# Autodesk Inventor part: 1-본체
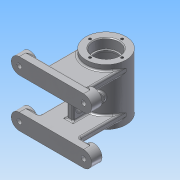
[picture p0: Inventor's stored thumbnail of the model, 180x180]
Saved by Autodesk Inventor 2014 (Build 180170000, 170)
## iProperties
Created: 2015-11
Part Number: 1-본체
Material: 알루미늄 6061
Document SubType Name: Modeling
Designer: 106-16
Density: 2.71 g/cm^3
Appearance: 알루미늄 - 평지
Mass: 358.546 g
Surface Area: 459.262 cm^2
Volume: 132.305 cm^3
Author: 106-16
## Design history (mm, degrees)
sketch "스케치1"
  geometry: C1 r 25 at (0, 0); 1 further point
  constraints: 1 centre point, 1 coincident
  dimensions: "d0" = 50 diameter of C1
extrude "돌출1" new body sketch "스케치1" stored distance "d1" = 70; taper "d2" = 0 deg
node "작업 평면2"
  node "작업 평면1"
sketch "스케치2"
  geometry: L1 (-40, 40)-(40, 40); L2 (40, 20)-(-40, 20); L3 (-40, -20)-(40, -20); L4 (40, -40)-(-40, -40); A1 r 10 centre (40, 30) between (40, 20) and (40, 40); A2 r 10 centre (-40, 30) between (-40, 40) and (-40, 20); A3 r 10 centre (40, -30) between (40, -40) and (40, -20); A4 r 10 centre (-40, -30) between (-40, -20) and (-40, -40); 3 further points
  constraints: 8 end point, 8 point on circle, 8 tangent, 4 centre point, 3 parallel, 2 midpoint, 2 vertical alignment, 1 horizontal
  dimensions: "d5" = 80 distance of L1.start L1.end; "d6" = 10 radius of A2; "d7" = 80 distance of L3.start L3.end; "d8" = 10 radius of A4; "d9" = 40 distance from line of point (0, 0) L1; "d10" = 40 distance from line of point (0, 0) L4
extrude "돌출2" join sketch "스케치2" distance "d11" = 10; taper "d12" = 0 deg
sketch "스케치3"
  geometry: L1 (-40, 20)-(40, 20) reference; L2 (40, 40)-(-40, 40) reference; L3 (-40, -40)-(40, -40) reference; L4 (40, -20)-(-40, -20) reference; C1 r 10 at (-40, -30); C2 r 10 at (40, -30); C3 r 10 at (40, 30); C4 r 10 at (-40, 30); A1 r 10 centre (-40, -30) between (-40, -20) and (-40, -40) reference; A2 r 10 centre (40, 30) between (40, 20) and (40, 40) reference; A3 r 10 centre (-40, 30) between (-40, 40) and (-40, 20) reference; A4 r 10 centre (40, -30) between (40, -40) and (40, -20) reference; A5 r 10 centre (-40, -30) between (-40, -20) and (-40, -40) reference; 1 further point
  constraints: 4 centre point, 4 coincident
  dimensions: "d13" = 20 diameter of C1; "d14" = 20 diameter of C4; "d15" = 20 diameter of C3; "d16" = 20 diameter of C2
extrude "돌출3" join sketch "스케치3" distance "d17" = 3; taper "d18" = 0 deg
sketch "스케치4"
  geometry: L1 (40, -20)-(-40, -20) reference; L2 (40, 20)-(-40, 20) reference; L3 (-40, 40)-(40, 40) reference; L4 (-25, 20)-(-25, 28); L5 (-25, 28)-(25, 28); L6 (25, 28)-(25, 20); L7 (-25, -20)-(-25, -28); L8 (-25, -28)-(25, -28); L9 (25, -28)-(25, -20); A1 r 10 centre (-40, 30) between (-40, 40) and (-40, 20) reference; A2 r 10 centre (40, 30) between (40, 20) and (40, 40) reference; 3 further points
  constraints: 12 end point, 5 perpendicular, 4 point on line, 2 midpoint, 2 vertical alignment, 1 parallel
  dimensions: "d19" = 8 distance between parallel lines of L2 L5; "d20" = 50 distance of L4.end L5.end; "d21" = 8 distance of L7.start L7.end; "d22" = 50 distance of L7.end L8.end
extrude "돌출4" join sketch "스케치4" stored distance "d23" = 3; taper "d24" = 0 deg
node "작업 평면4"
  node "작업 평면3"
sketch "스케치5"
  geometry: L1 (40, 40)-(-40, 40) reference; L2 (-40, 20)-(40, 20) reference; L3 (40, -20)-(-40, -20) reference; L4 (-40, -40)-(40, -40) reference; L5 (-4, -20)-(-4, 20); L6 (4, 20)-(4, -20); A1 r 10 centre (-40, 30) between (-40, 40) and (-40, 20) reference; A2 r 10 centre (40, 30) between (40, 20) and (40, 40) reference; A3 r 10 centre (-40, -30) between (-40, -20) and (-40, -40) reference; A4 r 10 centre (40, -30) between (40, -40) and (40, -20) reference; 1 further point
  constraints: 4 end point, 4 point on line, 2 perpendicular
  dimensions: "d26" = 8 distance between parallel lines of L6 L5; "d27" = 4 distance from line of L5 point (0, 0)
extrude "돌출5" join sketch "스케치5" stored distance "d28" = 3; taper "d29" = 0 deg
sketch "스케치6"
  geometry: L1 (40, 20.322)-(40, 0) reference; L2 (12, 13.5)-(28, 13.5); L3 (28, 6.5)-(12, 6.5); L4 (55, 20)-(55, 70) reference; L5 (-15, 70)-(-15, 20) reference; L6 (0, 20.322)-(40, 20.322) reference; L7 (40, 20.322)-(40, 45) reference; L8 (40, 45)-(48, 45) reference; L9 (48, 45)-(48, 45) reference; L10 (40, 45)-(48, 45) reference; L11 (40, 45)-(40, 20.322) reference; L12 (40, 20.322)-(0, 20.322) reference; L13 (0, 20.322)-(0, 45) reference; L14 (-8, 45)-(0, 45) reference; L15 (-8, 45)-(-8, 45) reference; L16 (-8, 45)-(0, 45) reference; L17 (0, 45)-(0, 20.322) reference; L18 (40, -23)-(60, -23) reference; A1 r 3.5 centre (28, 10) between (28, 6.5) and (28, 13.5); A2 r 3.5 centre (12, 10) between (12, 13.5) and (12, 6.5); 3 further points
  constraints: 4 end point, 4 point on circle, 4 tangent, 2 centre point, 2 midpoint, 1 parallel, 1 perpendicular, 1 vertical alignment
  dimensions: "d30" = 23 dimension on A2 A1; "d31" = 3.5 radius of A1; "d32" = 33 vertical distance of A1.centre L18.start
extrude "돌출6" cut sketch "스케치6" stored distance "d33" = 3; taper "d34" = 0 deg
node "작업 평면5"
sketch "스케치7"
  geometry: L1 (-25, -35)-(25, -35) reference; 2 further points
  constraints: 1 other
  dimensions: "d35" = 25 horizontal distance of point (0, 0) L1.start; "d36" = 35 distance from line of point (0, 0) L1
feature "엠보싱1" sketch "스케치7" dims "d37" = 0.5, "d38" = 0
node "작업 평면7"
  node "작업 평면6"
sketch "스케치8"
  geometry: C1 r 5 at (0, 0); 1 further point
  constraints: 1 centre point, 1 coincident
  dimensions: "d40" = 10 diameter of C1
extrude "돌출7" join sketch "스케치8" stored distance "d41" = 3; taper "d42" = 0 deg
node "작업 평면8"
sketch "스케치9"
  geometry: L1 (0, 0)-(25, 0); L2 (0, 0)-(12.5, -21.651); L3 (0, 0)-(0, -25); A1 r 25 centre (0, 0) between (25, 0) and (12.5, -21.651) reference; 2 further points
  constraints: 6 end point, 3 point on circle, 1 coincident, 1 horizontal, 1 perpendicular
  dimensions: "d44" = 30 deg angle of L2 L3
node "작업 평면10"
  node "작업 평면9"
sketch "스케치10"
  geometry: C1 r 6 at (0, 0); 1 further point
  constraints: 1 centre point, 1 coincident
  dimensions: "d46" = 12 diameter of C1
extrude "돌출8" join sketch "스케치10" stored distance "d47" = 3; taper "d48" = 0 deg
sketch "스케치11"
  geometry: C1 r 10 at (0, 0) reference; C2 r 10 at (0, -60) reference; C3 r 10 at (80, 0) reference; C4 r 10 at (80, -60) reference; 5 further points
  constraints: 4 coincident
hole "구멍1" sketch "스케치11" at (0, 0), (0, -60), (80, -60), (80, 0) diameter "d49" = 6; stored, may be unused: countersink angle "d53" = 90 deg, drill point angle "d55" = 0 deg; dims "d50" = 6, "d51" = 12, "d52" = 4, "d54" = 13
hole "구멍2" diameter "d58" = 28; stored, may be unused: countersink angle "d62" = 90 deg, drill point angle "d64" = 0 deg; dims "d56" = 10, "d57" = 10, "d59" = 6, "d60" = 32, "d61" = 12, "d63" = 13
hole "구멍3" diameter "d67" = 28; stored, may be unused: countersink angle "d71" = 90 deg, drill point angle "d73" = 0 deg; dims "d65" = 10, "d66" = 10, "d68" = 6, "d69" = 32, "d70" = 12, "d72" = 13
node "작업 평면11"
sketch "스케치12"
  geometry: L1 (-14, -23)-(14, -23) reference; L2 (14, 23)-(-14, 23) reference; L3 (14, -23)-(14, 23) reference; L4 (-14, -23)-(-14, 23) reference; L5 (0, 21)-(0, -21); L6 (21, 18)-(21, -18); L7 (0, 21)-(18, 21); L8 (0, -21)-(18, -21); A1 r 3 centre (18, 18) between (21, 18) and (18, 21); A2 r 3 centre (18, -18) between (18, -21) and (21, -18); 2 further points
  constraints: 8 end point, 4 point on circle, 4 tangent, 2 centre point, 2 parallel, 2 perpendicular, 1 coincident, 1 equal radius, 1 midpoint
  dimensions: "d75" = 42 distance of L5.start L5.end; "d76" = 42 diameter of L6 L5; "d77" = 3 radius of A1
revolve "회전1" sketch "스케치12" stored, may be unused: angle "d78" = 90 deg
sketch "스케치13"
  geometry: C1 r 16 at (0, 0) reference; C2 r 25 at (0, 0) reference; A1 r 20 centre (0, 0) between (0, 20) and (20, 0); 2 further points
  constraints: 4 point on circle, 2 horizontal alignment, 2 vertical alignment, 1 centre point, 1 coincident
  dimensions: "d79" = 40 diameter of A1
hole "구멍4" sketch "스케치13" at (0, 20), (20, 0), (-20, 0), (0, -20) diameter "d80" = 3.242; stored, may be unused: countersink angle "d84" = 90 deg, drill point angle "d86" = 118 deg; dims "d81" = 8, "d82" = 4, "d83" = 2, "d85" = 10
node "작업 평면12"
hole "구멍5" diameter "d89" = 5.188; stored, may be unused: countersink angle "d93" = 90 deg, drill point angle "d95" = 0 deg; dims "d87" = 10, "d88" = 10, "d90" = 8, "d91" = 4, "d92" = 2, "d94" = 10
hole "구멍6" diameter "d98" = 5.188; stored, may be unused: countersink angle "d102" = 90 deg, drill point angle "d104" = 0 deg; dims "d96" = 10, "d97" = 10, "d99" = 8, "d100" = 4, "d101" = 2, "d103" = 10
fillet "모깎기1" dims "d105" = 0.3, "d106" = 3.5
chamfer "모따기1" distance "d107" = 1; stored, may be unused: second distance "d108" = 2, angle "d109" = 45 deg
fillet "모깎기2" dims "d110" = 2
fillet "모깎기3" dims "d111" = 2
node "솔리드1"
mirror "대칭1"
node "투영된 루프1"
node "투영된 루프2"
node "투영된 루프3"
node "투영된 루프4"
node "투영된 루프5"
node "투영된 루프6"
node "투영된 루프7"
node "투영된 루프8"
node "투영된 루프9"
other parameters: "d3" = 0, "d4" = -68, "d39" = 3, "d45" = 3, "d74" = 0
